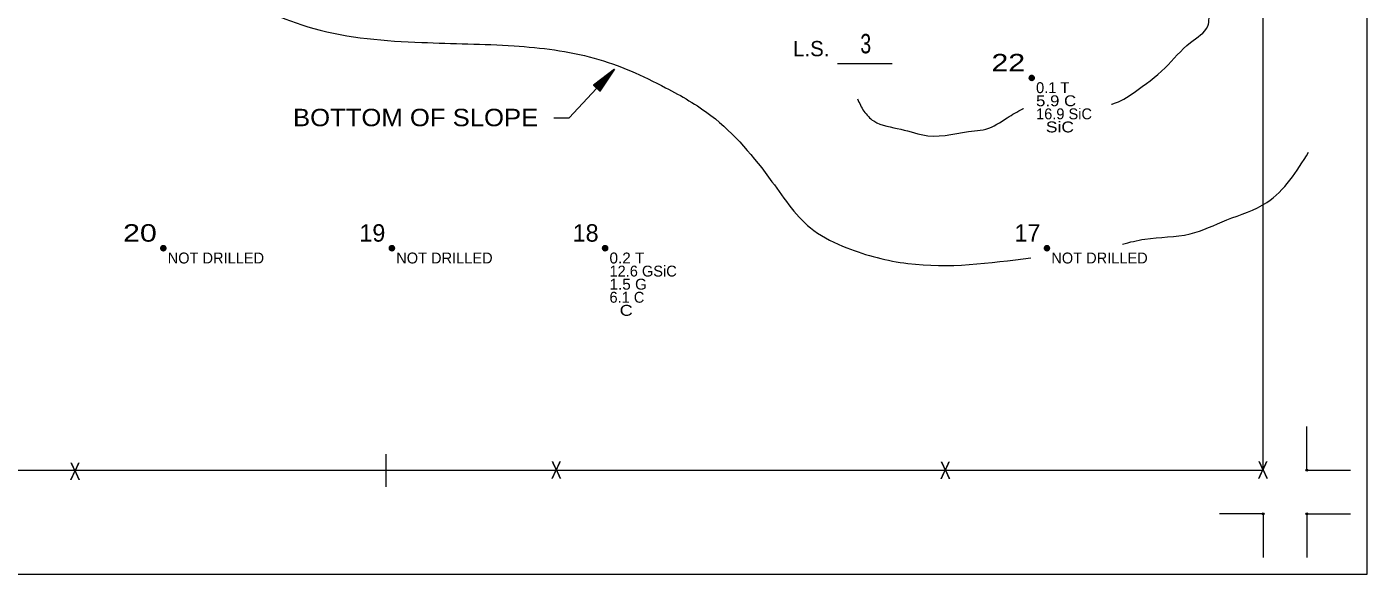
# Model space of a CAD drawing. Extents: x -496 to 480, y -450 to 700.
# Drawn here: x -165 to 450, y -450 to -199 of the extents above; entities that cross this region are included whole.
import ezdxf
from ezdxf.enums import TextEntityAlignment as Align

# ---------------------------------------------------------------- set-up
doc = ezdxf.new("R2010")
doc.units = 0
doc.header["$LTSCALE"] = 2
doc.header["$PDMODE"] = 32
doc.header["$PDSIZE"] = 1
for name, color, linetype, lineweight in [('1', 7, 'Continuous', 13), ('2', 7, 'Continuous', 35), ('3', 7, 'Continuous', 13), ('4', 7, 'Continuous', 25)]:
    doc.layers.add(name, color=color, linetype=linetype, lineweight=lineweight)

msp = doc.modelspace()

# ---------------------------------------------------------------- linework, layer by layer
at = {"layer": '1'}
for p, q in [((207.114, -215.907), (232.114, -215.907)), ((422.281, -402.333), (422.281, -382.333)), ((-0.017, -395.027), (-0.017, -410.027)), ((-402.391, -402.333), (402.281, -402.333)), ((422.281, -402.333), (442.281, -402.333)), ((402.281, -422.333), (382.281, -422.333)), ((402.281, -422.333), (402.281, -442.333)), ((422.281, -422.333), (422.281, -442.333)), ((422.281, -422.333), (442.281, -422.333)), ((-450.017, -450.027), (449.983, -450.027))]:
    msp.add_line(p, q, dxfattribs=at)
for points in [[(449.983, -450.027), (449.983, 399.973), (449.983, 699.973), (-450.017, 699.973), (-450.017, 49.973), (-450.017, -450.027)], [(402.281, -402.333), (402.281, 402.339), (-402.391, 402.339)]]:
    msp.add_lwpolyline(points, dxfattribs=at)
for p in [(422.281, -402.333), (402.281, -422.333), (422.281, -422.333)]:
    msp.add_point(p, dxfattribs=at)
at = {"layer": '2'}
for centre in [(296.124, -222.453), (-102.135, -300.552), (2.67, -300.552), (100.488, -300.552), (303.111, -300.552)]:
    msp.add_circle(centre, 1, dxfattribs=at)
for points in [[(296.113, -221.566), (296.843, -221.97), (296.995, -222.819), (296.31, -223.347), (295.501, -223.116), (295.214, -222.358), (295.461, -221.796), (296.034, -221.628), (296.708, -222.122), (296.692, -222.864), (296.175, -223.122), (295.652, -222.953), (295.428, -222.307), (296.012, -221.841), (296.45, -222.375), (296.411, -222.858), (295.782, -222.723), (295.928, -222.088), (296.22, -222.639)], [(-102.146, -299.665), (-101.416, -300.069), (-101.264, -300.918), (-101.949, -301.446), (-102.758, -301.215), (-103.045, -300.457), (-102.798, -299.895), (-102.225, -299.727), (-101.551, -300.221), (-101.567, -300.963), (-102.084, -301.221), (-102.607, -301.052), (-102.831, -300.406), (-102.247, -299.94), (-101.809, -300.474), (-101.848, -300.957), (-102.477, -300.822), (-102.331, -300.187), (-102.039, -300.738)], [(2.659, -299.665), (3.389, -300.069), (3.541, -300.918), (2.856, -301.446), (2.047, -301.215), (1.76, -300.457), (2.007, -299.895), (2.58, -299.727), (3.254, -300.221), (3.238, -300.963), (2.721, -301.221), (2.198, -301.052), (1.974, -300.406), (2.558, -299.94), (2.996, -300.474), (2.957, -300.957), (2.328, -300.822), (2.474, -300.187), (2.766, -300.738)], [(100.477, -299.665), (101.207, -300.069), (101.359, -300.918), (100.674, -301.446), (99.865, -301.215), (99.578, -300.457), (99.825, -299.895), (100.398, -299.727), (101.072, -300.221), (101.056, -300.963), (100.539, -301.221), (100.016, -301.052), (99.792, -300.406), (100.376, -299.94), (100.814, -300.474), (100.775, -300.957), (100.146, -300.822), (100.292, -300.187), (100.584, -300.738)], [(303.1, -299.665), (303.83, -300.069), (303.982, -300.918), (303.297, -301.446), (302.488, -301.215), (302.201, -300.457), (302.448, -299.895), (303.021, -299.727), (303.695, -300.221), (303.679, -300.963), (303.162, -301.221), (302.639, -301.052), (302.415, -300.406), (302.999, -299.94), (303.437, -300.474), (303.398, -300.957), (302.769, -300.822), (302.915, -300.187), (303.207, -300.738)]]:
    msp.add_spline(points, degree=3, dxfattribs=at)
at = {"layer": '3'}
msp.add_line((-397.389, -402.333), (402.281, -402.333), dxfattribs=at)
for points in [[(402.334, 128.248), (383.156, 141.817), (361.58, 167.359), (316.03, 204.874), (294.455, 212.058), (261.691, 224.828), (175.387, 224.828), (143.423, 227.223), (125.043, 232.012), (105.066, 233.608), (72.302, 239.196), (51.525, 250.37), (31.548, 256.756), (-6.81, 256.756), (-62.747, 242.389), (-112.292, 210.461), (-141.859, 162.57), (-160.239, 117.872), (-180.217, 46.833), (-177.819, -26.6), (-172.225, -83.271), (-165.033, -115.996), (-149.85, -153.511), (-130.672, -161.493), (-98.707, -171.071), (-74.734, -182.245), (-33.18, -199.806), (16.364, -206.191), (58.717, -207.787), (95.476, -213.375), (128.24, -226.944), (149.017, -239.715), (176.985, -270.046), (196.164, -292.395), (211.347, -300.377), (239.316, -307.56), (295.735, -304.937)], [(332.652, -234.524), (333.309, -234.347), (343.071, -229.097), (357.338, -217.846), (368.977, -206.221), (376.861, -198.72), (376.861, -191.22), (373.858, -185.22), (365.222, -179.97), (344.573, -158.594), (338.941, -147.344), (336.688, -137.968), (338.566, -125.218), (342.32, -116.968), (356.212, -83.216), (359.966, -67.841)], [(216.237, -232.077), (219.173, -237.722), (223.678, -242.222), (236.068, -245.972), (248.458, -248.972), (269.859, -246.722), (275.115, -245.972), (284.876, -240.722), (292.01, -236.597), (292.316, -236.425)], [(337.695, -298.673), (347.995, -296.386), (368.772, -293.991), (385.553, -287.606), (403.933, -279.624), (423.111, -256.477)]]:
    msp.add_spline(points, degree=3, dxfattribs=at)
at = {"layer": '4', "lineweight": 13}
msp.add_lwpolyline([(76.919, -240.727), (84.022, -240.727), (104.803, -218.393)], dxfattribs=at)
at = {"layer": '4'}
msp.add_lwpolyline([(104.803, -218.393), (95.164, -225.816), (98.092, -228.541)], close=True, dxfattribs=at)
msp.add_lwpolyline([(95.317, -225.825), (104.411, -218.813), (98.083, -228.31), (95.475, -225.911), (103.909, -219.352), (98.09, -228.051), (95.701, -225.888), (103.379, -219.922), (98.063, -227.76), (95.947, -225.94), (102.761, -220.555), (98.083, -227.453), (96.255, -225.929), (102.022, -221.316), (98.026, -227.133), (96.592, -225.948), (101.227, -222.14), (97.979, -226.708), (96.942, -225.919), (100.324, -223.015), (98.024, -226.278), (97.352, -225.858), (99.323, -224.121), (98.022, -225.744)], dxfattribs=at)

# ---------------------------------------------------------------- texts
at = {"layer": '1', "width": 0.75}
msp.add_text('3', height=8.89, dxfattribs=at).set_placement((220.003, -211.189), align=Align.CENTER)
at = {"layer": '1'}
msp.add_text('L.S.', height=7, dxfattribs=at).set_placement((195.033, -212.53), align=Align.CENTER)
at = {"layer": '2', "width": 1.3}
for s, p in [(' 22', (293.123, -219.453)), (' 20', (-105.136, -297.552))]:
    msp.add_text(s, height=8, dxfattribs=at).set_placement(p, align=Align.RIGHT)
at = {"layer": '2'}
for s, p in [('0.1 T      ', (298.124, -229.453)), ('16.9 SiC   ', (298.124, -241.453)), ('NOT DRILLED', (-100.135, -307.552)), ('NOT DRILLED', (4.67, -307.552)), ('NOT DRILLED', (305.111, -307.552)), ('12.6 GSiC  ', (102.488, -313.552)), ('6.1 C      ', (102.488, -325.552))]:
    msp.add_text(s, height=5, dxfattribs=at).set_placement(p)
for s, width, p in [('5.9 C      ', 1.15, (298.124, -235.453)), ('  SiC      ', 1.2, (298.124, -247.453)), ('0.2 T      ', 1.05, (102.488, -307.552)), ('1.5 G      ', 1.05, (102.488, -319.552)), ('  C        ', 1.25, (102.488, -331.552))]:
    msp.add_text(s, height=5, dxfattribs=dict(at, width=width)).set_placement(p)
for s, p in [(' 19', (-0.331, -297.552)), (' 18', (97.487, -297.552)), (' 17', (300.11, -297.552))]:
    msp.add_text(s, height=8, dxfattribs=at).set_placement(p, align=Align.RIGHT)
at = {"layer": '3', "width": 0.7}
for p in [(-142.658, -406.852), (78.059, -406.288), (256.479, -406.361), (402.164, -406.222)]:
    msp.add_text('X', height=8, dxfattribs=at).set_placement(p, align=Align.CENTER)
at = {"layer": '4', "width": 1.1}
msp.add_text('BOTTOM OF SLOPE', height=8, dxfattribs=at).set_placement((13.566, -244.621), align=Align.CENTER)

doc.saveas('drawing.dxf')
